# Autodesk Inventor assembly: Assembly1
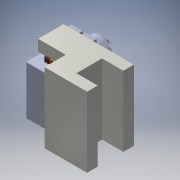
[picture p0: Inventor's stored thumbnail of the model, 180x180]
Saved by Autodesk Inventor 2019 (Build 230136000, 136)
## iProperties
Created: 2020-02
Part Number: Assembly1
Document SubType Name: Assembly
Designer: ash
Author: ash
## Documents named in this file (3)
- F:\autodesk\Assembly1.iam
- F:\autodesk\Part2.ipt
- C:\Users\ash\Downloads\Servo-MG90S (1).ipt
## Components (2 placed, 2 different names)
1. Part2:1 — Mate:1, Mate:2
2. Servo-MG90S (1):1 — Mate:1, Mate:2
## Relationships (2: Mate 2)
- Mate:1: Part2:1 ↔ Servo-MG90S (1):1
- Mate:2: Part2:1 ↔ Servo-MG90S (1):1
